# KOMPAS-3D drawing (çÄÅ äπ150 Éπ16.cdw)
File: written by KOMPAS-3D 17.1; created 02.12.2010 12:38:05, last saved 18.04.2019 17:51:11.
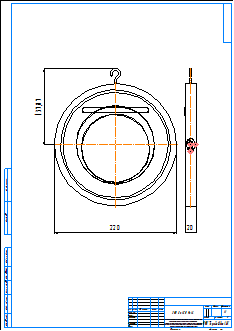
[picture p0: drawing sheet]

Sheet 1: A2, portrait

Title block, sheet 1: name: ЗОП Ду150 Ру16; material: Внимание! Данный продукт является объектом авторского права ООО «Торговый Дом АДЛ». / Запрещается изменение, копирование, распространение / (в том числе путем копирования на другие сайты и ресурсы в Интернете) / или любое иное использование информации и объектов без предварительного / согласия правообладателя (ООО «Торговый Дом АДЛ»).; scale: 1:1; sheets: 1; organisation: ООО "Торговый дом АДЛ"; sheet format: A2; stored path: \\adlc.lan\data\АДЛ_ПКД\3D-модели\ADL production\Клапаны обратные ГРАНЛОК\ЗОП\KOMPAS 2D\ЗОП Ду150 Ру16.cdw

Views: Спереди 1, Проекционный вид 2
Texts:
  bsv
  adl
Dimensions and other numbers on the sheet: 220; 20; 137,87; 1:1; 1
